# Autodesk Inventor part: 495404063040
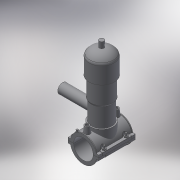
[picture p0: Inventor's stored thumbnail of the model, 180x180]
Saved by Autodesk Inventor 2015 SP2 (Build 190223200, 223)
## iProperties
Created: 2017-07
Part Number: 495404063040
Material: Generic
Description: PLASSON TAPPING VALVE 63-40
Document SubType Name: Modeling
Designer: KIM
Density: 1 g/cm^3
Appearance: Default
Author: KIM
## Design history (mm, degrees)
derived "495404-4954S4.ipt"
feature "Solid1::495404-4954S4.ipt"
feature "Solid2::495404-4954S4.ipt"
tag "TaggingFeature1"
body "Solid1"
body "Solid2"
other parameters: "d0" = 63, "d2" = 99, "d3" = 15.75, "d4" = 118, "d5" = 0, "d6" = 0.1, "d8" = 0, "d19" = 6, "d20" = 6, "d21" = 70.8, "d23" = 0, "d24" = 35.4, "d26" = 0, "d27" = 3, "d28" = 3, "d29" = 3, "d30" = 21, "d31" = 6, "d32" = 0, "d33" = 0, "d34" = 0.6, "d40" = 42.588, "d47" = 86.95, "d70" = 15, "d72" = 0, "d73" = 6, "d75" = 5, "d76" = 0, "d77" = 3.15, "d78" = 61.5, "d79" = 15, "d80" = 47.2, "d82" = 5 deg, "d84" = 4, "d85" = 14, "d86" = 0, "d87" = 3, "d88" = 0, "d89" = 1, "d90" = 1, "d91" = 94.4, "d92" = 0, "d93" = 0.5, "d94" = 33.15789, "d96" = 84.357, "d97" = 2.36, "d98" = 0, "d120" = 140 deg, "d121" = 24.228, "d122" = 20 deg, "d123" = 163.8, "d124" = 49.14, "d126" = 0, "d143" = 64.89, "d145" = 14.53846, "d149" = 0.945, "d150" = 15.99231, "d153" = 118, "d154" = 0, "d156" = 40.95, "d157" = 160 deg, "d159" = 3.78, "d161" = 0.945, "d162" = 70.8, "d163" = 0, "d164" = 31.5, "d167" = 6.3, "d168" = 39.95122, "d170" = 3, "d172" = 0, "d173" = 1, "d175" = 31.5, "d176" = 20 deg, "d177" = 4.41, "d178" = 18.9, "d180" = 0, "d183" = 7.56, "d184" = 3.528, "d185" = 38.35, "d186" = 38.35, "d187" = 40.95, "d188" = 5.67, "d189" = 4.41, "d190" = 0, "d191" = 61.425, "d193" = 6.8, "d194" = 2.95, "d195" = 90 deg, "d197" = 0, "d199" = 0, "d205" = 14.64, "d206" = 81.33333, "d207" = 244, "d208" = 224.48, "d209" = 207.4, "d210" = 200.08, "d211" = 146.4, "d212" = 85.4, "d213" = 65.88, "d214" = 73.2, "d216" = 19.52, "d217" = 70.76, "d218" = 80.52, "d220" = 63, "d222" = 0, "d223" = 81.9, "d224" = 137, "d225" = 46, "d229" = 137, "d230" = 0, "d_" = 63, "B_" = 99, "H_" = 137, "L_" = 118, "d_t" = 6, "H_1" = 46, "H_2" = 244, "d148" = 0.945, "d160" = 0.945, "d169" = 3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
